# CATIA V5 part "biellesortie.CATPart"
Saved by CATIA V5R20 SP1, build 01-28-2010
Part number: biellesortie
Bounding box of the stored display mesh (mm): x 48 to 87, y 0 to 40, z 28.093 to 41.907
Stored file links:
  E:\EDELI\gcausse\Edeli_2012_685_gcausse\biellesortie.CATPart
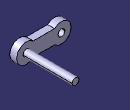
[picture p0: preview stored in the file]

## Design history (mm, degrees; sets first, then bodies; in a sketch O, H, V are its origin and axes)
Parameters
  long = 0.025
  diamtrou = 0.005
Body1 (main body)
  Sketch1 on zx-plane, origin (0, 0, 0), H (-1, 0, 0), V (0, 0, 1)
    line L1 (-59.899, 40) -> (-75.101, 40)
    line L2 (-59.899, 30) -> (-75.101, 30)
    arc A1 centre (-55, 35) radius 7 from (-59.899, 40) to (-59.899, 30) cw
    point P5 (-55, 35)
    point P6 (-50.101, 30)
    arc A2 centre (-80, 35) radius 7 from (-75.101, 40) to (-75.101, 30) ccw
    point P7 (-80, 35)
    circle A3 centre (-55, 35) radius 2.5
    distance P7 L1 = 5
    distance P5 L2 = 5
    distance L2 L1 = 10
    radius A1 = 7
    radius A2 = 7
    distance P5 P7 = 25 {= long}
    radius A3 = 2.5
    horizontal: L1 H, L2 H
    coincidence: A1 P6, P6 L2
  Pad1: profile Sketch1, direction (0, 1, 0), length 5
  Sketch2 on end face of Pad1, origin (0, 5, 0), H (-1, 0, 0), V (0, 0, 1)
    circle A1 centre (-80, 35) radius 2.5
    reference projected arc E1 centre (-80, 35) radius 7 from (-75.101, 40) to (-75.101, 30) ccw from edge [face of Pad1 from Sketch1.A2 | end face of Pad1]
    reference projected arc E2 centre (-80, 35) radius 7 from (-75.101, 40) to (-75.101, 30) ccw from edge [face of Pad1 from Sketch1.A2 | end face of Pad1]
    radius A1 = 2.5
    radius E2 = 7 (reference)
    concentricity: A1 E1
  Pad2: profile Sketch2, direction (0, 1, 0), length 35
